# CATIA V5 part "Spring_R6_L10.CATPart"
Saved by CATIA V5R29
Part number: Spring_R6_L10
Definition: Cadenas PARTsolutions
Source: Unknown
Description: Economy Torsion Spring
Bounding box of the stored display mesh (mm): x -196 to 70, y -33.2 to 33.192, z -45.65 to 4.15
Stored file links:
  C:\가치같이\SmartFactory_BoxErectorConveyor\Boxing(under)\Spring_R6_L10.CATPart
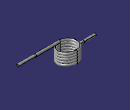
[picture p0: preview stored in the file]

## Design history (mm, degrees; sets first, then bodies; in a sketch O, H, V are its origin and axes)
Body1 "C-UA180R6-5-1.0-C-LC10-RC10" (main body)
  Solid1: solid without history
